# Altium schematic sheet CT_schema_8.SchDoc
size 226 x 144 mm
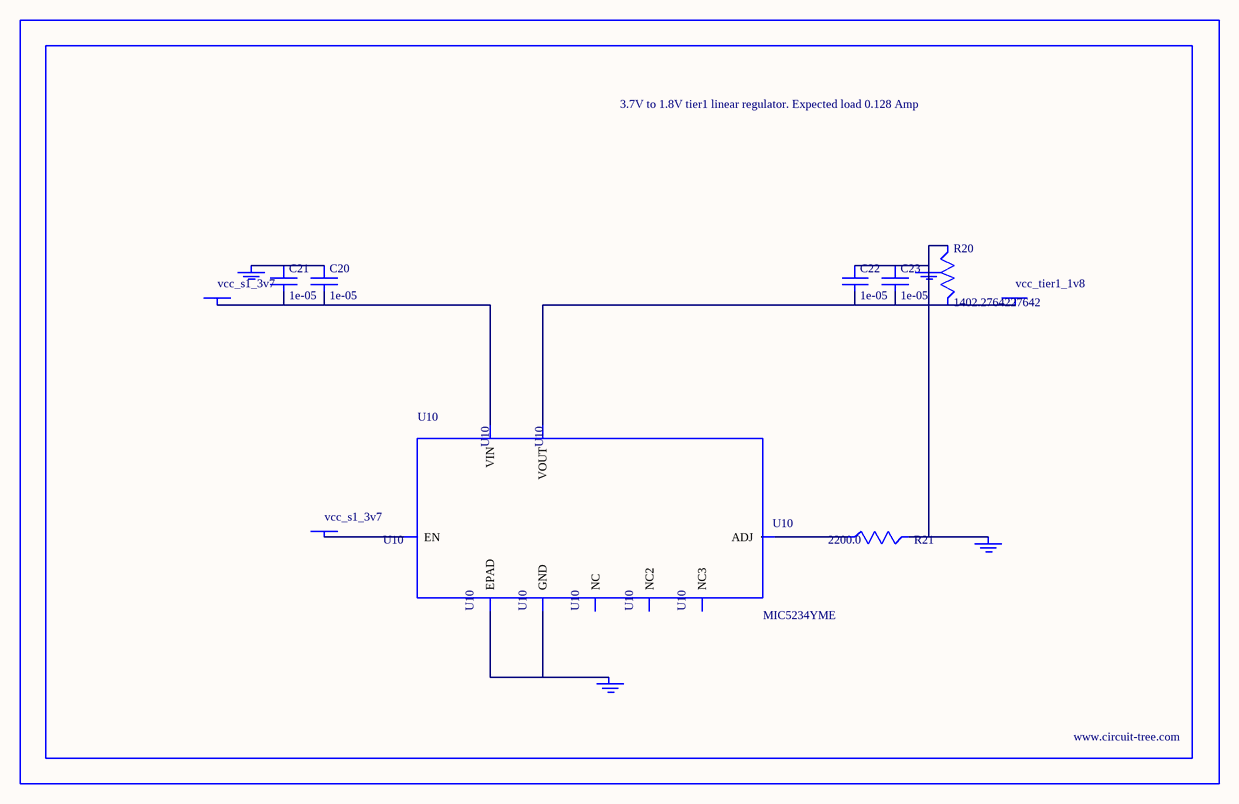
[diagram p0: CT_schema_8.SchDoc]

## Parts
BORDER7  (no value)
C20  1e-05  [C1210]
C21  1e-05  [C1210]
C22  1e-05  [C1210]
C23  1e-05  [C1210]
GND_INSTANCE_7_0  (no value)
GND_INSTANCE_7_1  (no value)
GND_INSTANCE_7_2  (no value)
GND_INSTANCE_7_3  (no value)
POWER_INSTANCE_7_0  vcc_tier1_1v8
POWER_INSTANCE_7_1  vcc_s1_3v7
POWER_INSTANCE_7_2  vcc_s1_3v7
R20  1402.2764227642  [R0603]
R21  2200.0  [R0603]
U10  MIC5234YME  [SOIC-8_EP]

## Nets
NetC20_1: C20.1 C21.1 GND_INSTANCE_7_3.0(GND)
NetC20_2: C20.2 C21.2 POWER_INSTANCE_7_2.0(PWR) U10.8(VIN)
NetC22_1: C22.1 C23.1 GND_INSTANCE_7_0.0(GND) GND_INSTANCE_7_1.0(GND) R20.1 R21.2
NetC22_2: C22.2 C23.2 POWER_INSTANCE_7_0.0(PWR) R20.2 U10.1(VOUT)
NetGND_INSTANCE_7_2_0: GND_INSTANCE_7_2.0(GND) U10.7(GND) U10.EPAD
NetPOWER_INSTANCE_7_1_0: POWER_INSTANCE_7_1.0(PWR) U10.5(EN)
NetR21_1: R21.1 U10.4(ADJ)

Not connected (* = marked no-connect by the designer): U10 2(NC) 3(NC2) 6(NC3)

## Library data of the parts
BORDER7 = BORDER_PAGE7
C20-C23 = C1210C106K5PACTU
GND_INSTANCE_7_0-GND_INSTANCE_7_3 = GND
POWER_INSTANCE_7_0-POWER_INSTANCE_7_2 = PWR
R20 = R20
R21 = RC0603JR-072K2L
